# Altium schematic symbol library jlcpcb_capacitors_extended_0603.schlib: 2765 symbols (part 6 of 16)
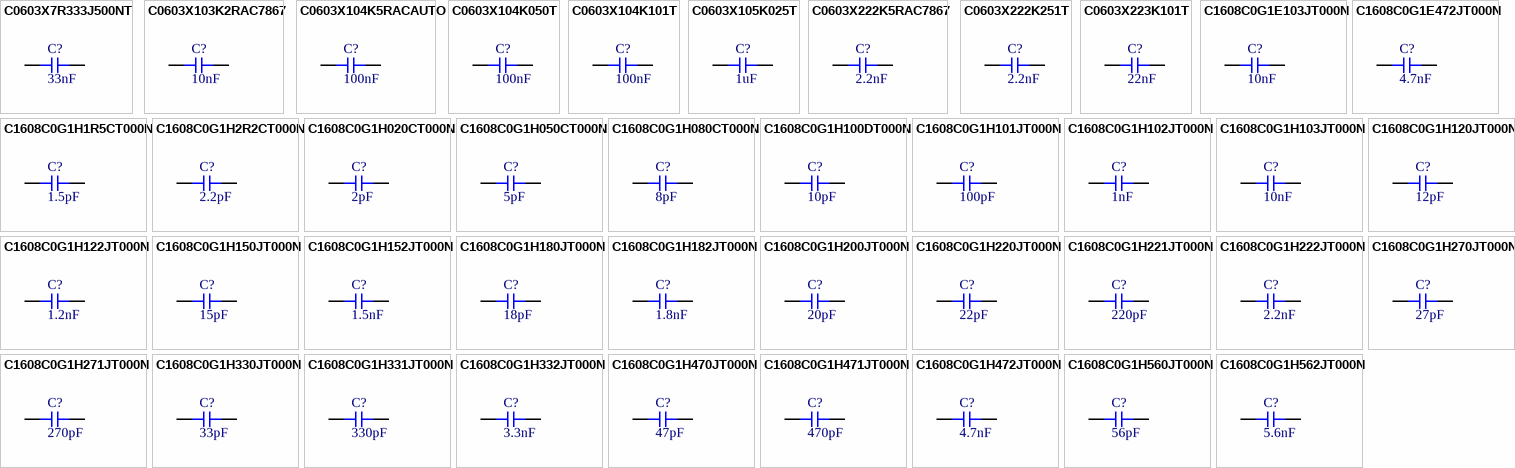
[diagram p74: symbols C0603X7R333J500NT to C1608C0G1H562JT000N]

## C1608C0G1H220JT000N
designator C?  Capacitance: 22pF  (hidden comment: *)
Capacitor, Ceramic (MLCC), 22pF, ±5%, 50V, C0G, ±5%, SMD 0603; Manufacturer: TDK; Manufacturer Part Number: C1608C0G1H220JT000N
footprint CAP-0603 (0603 (1608M) Capacitor)
pins: 1, 2

## C1608C0G1H221JT000N
designator C?  Capacitance: 220pF  (hidden comment: *)
Capacitor, Ceramic (MLCC), 220pF, ±5%, 50V, C0G, ±5%, SMD 0603; Manufacturer: TDK; Manufacturer Part Number: C1608C0G1H221JT000N
footprint CAP-0603 (0603 (1608M) Capacitor)
pins: 1, 2

## C1608C0G1H222JT000N
designator C?  Capacitance: 2.2nF  (hidden comment: *)
Capacitor, Ceramic (MLCC), 2.2nF, ±5%, 50V, C0G, ±5%, SMD 0603; Manufacturer: TDK; Manufacturer Part Number: C1608C0G1H222JT000N
footprint CAP-0603 (0603 (1608M) Capacitor)
pins: 1, 2

## C1608C0G1H270JT000N
designator C?  Capacitance: 27pF  (hidden comment: *)
Capacitor, Ceramic (MLCC), 27pF, ±5%, 50V, C0G, ±5%, SMD 0603; Manufacturer: TDK; Manufacturer Part Number: C1608C0G1H270JT000N
footprint CAP-0603 (0603 (1608M) Capacitor)
pins: 1, 2

## C1608C0G1H271JT000N
designator C?  Capacitance: 270pF  (hidden comment: *)
Capacitor, Ceramic (MLCC), 270pF, ±5%, 50V, C0G, ±5%, SMD 0603; Manufacturer: TDK; Manufacturer Part Number: C1608C0G1H271JT000N
footprint CAP-0603 (0603 (1608M) Capacitor)
pins: 1, 2

## C1608C0G1H330JT000N
designator C?  Capacitance: 33pF  (hidden comment: *)
Capacitor, Ceramic (MLCC), 33pF, ±5%, 50V, C0G, ±5%, SMD 0603; Manufacturer: TDK; Manufacturer Part Number: C1608C0G1H330JT000N
footprint CAP-0603 (0603 (1608M) Capacitor)
pins: 1, 2

## C1608C0G1H331JT000N
designator C?  Capacitance: 330pF  (hidden comment: *)
Capacitor, Ceramic (MLCC), 330pF, ±5%, 50V, C0G, ±5%, SMD 0603; Manufacturer: TDK; Manufacturer Part Number: C1608C0G1H331JT000N
footprint CAP-0603 (0603 (1608M) Capacitor)
pins: 1, 2

## C1608C0G1H332JT000N
designator C?  Capacitance: 3.3nF  (hidden comment: *)
Capacitor, Ceramic (MLCC), 3.3nF, ±5%, 50V, C0G, ±5%, SMD 0603; Manufacturer: TDK; Manufacturer Part Number: C1608C0G1H332JT000N
footprint CAP-0603 (0603 (1608M) Capacitor)
pins: 1, 2

## C1608C0G1H470JT000N
designator C?  Capacitance: 47pF  (hidden comment: *)
Capacitor, Ceramic (MLCC), 47pF, ±5%, 50V, C0G, ±5%, SMD 0603; Manufacturer: TDK; Manufacturer Part Number: C1608C0G1H470JT000N
footprint CAP-0603 (0603 (1608M) Capacitor)
pins: 1, 2

## C1608C0G1H471JT000N
designator C?  Capacitance: 470pF  (hidden comment: *)
Capacitor, Ceramic (MLCC), 470pF, ±5%, 50V, C0G, ±5%, SMD 0603; Manufacturer: TDK; Manufacturer Part Number: C1608C0G1H471JT000N
footprint CAP-0603 (0603 (1608M) Capacitor)
pins: 1, 2

## C1608C0G1H472JT000N
designator C?  Capacitance: 4.7nF  (hidden comment: *)
Capacitor, Ceramic (MLCC), 4.7nF, ±5%, 50V, C0G, ±5%, SMD 0603; Manufacturer: TDK; Manufacturer Part Number: C1608C0G1H472JT000N
footprint CAP-0603 (0603 (1608M) Capacitor)
pins: 1, 2

## C1608C0G1H560JT000N
designator C?  Capacitance: 56pF  (hidden comment: *)
Capacitor, Ceramic (MLCC), 56pF, ±5%, 50V, C0G, ±5%, SMD 0603; Manufacturer: TDK; Manufacturer Part Number: C1608C0G1H560JT000N
footprint CAP-0603 (0603 (1608M) Capacitor)
pins: 1, 2

## C1608C0G1H562JT000N
designator C?  Capacitance: 5.6nF  (hidden comment: *)
Capacitor, Ceramic (MLCC), 5.6nF, ±5%, 50V, C0G, ±5%, SMD 0603; Manufacturer: TDK; Manufacturer Part Number: C1608C0G1H562JT000N
footprint CAP-0603 (0603 (1608M) Capacitor)
pins: 1, 2

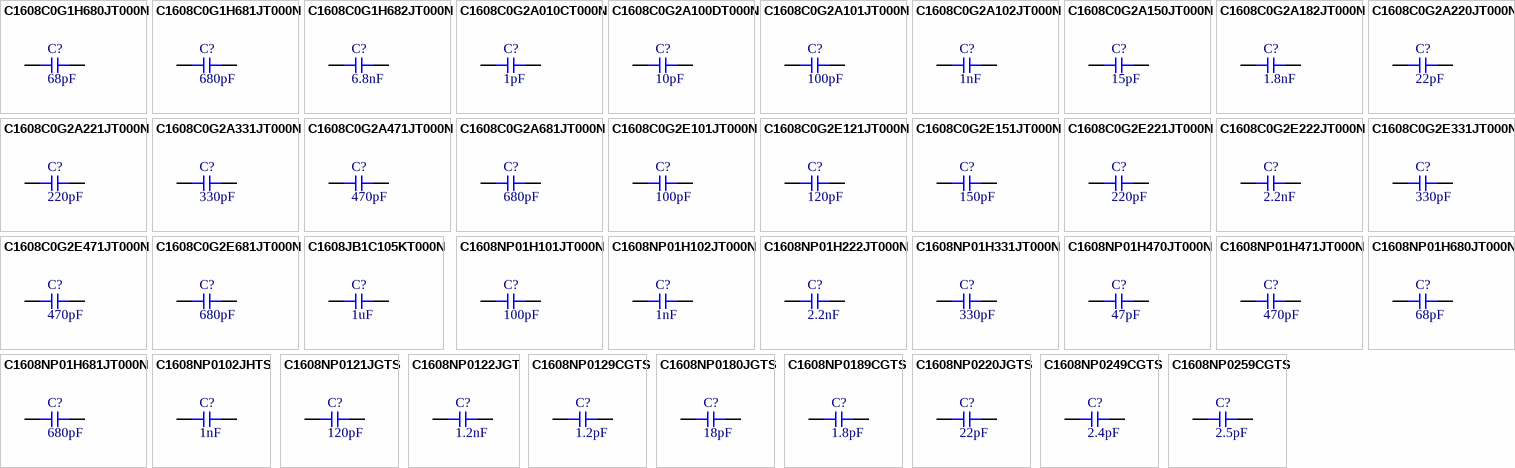
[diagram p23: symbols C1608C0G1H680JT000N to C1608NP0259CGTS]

## C1608C0G1H680JT000N
designator C?  Capacitance: 68pF  (hidden comment: *)
Capacitor, Ceramic (MLCC), 68pF, ±5%, 50V, C0G, ±5%, SMD 0603; Manufacturer: TDK; Manufacturer Part Number: C1608C0G1H680JT000N
footprint CAP-0603 (0603 (1608M) Capacitor)
pins: 1, 2

## C1608C0G1H681JT000N
designator C?  Capacitance: 680pF  (hidden comment: *)
Capacitor, Ceramic (MLCC), 680pF, ±5%, 50V, C0G, ±5%, SMD 0603; Manufacturer: TDK; Manufacturer Part Number: C1608C0G1H681JT000N
footprint CAP-0603 (0603 (1608M) Capacitor)
pins: 1, 2

## C1608C0G1H682JT000N
designator C?  Capacitance: 6.8nF  (hidden comment: *)
Capacitor, Ceramic (MLCC), 6.8nF, ±5%, 50V, C0G, ±5%, SMD 0603; Manufacturer: TDK; Manufacturer Part Number: C1608C0G1H682JT000N
footprint CAP-0603 (0603 (1608M) Capacitor)
pins: 1, 2

## C1608C0G2A010CT000N
designator C?  Capacitance: 1pF  (hidden comment: *)
Capacitor, Ceramic (MLCC), 1pF, ±0.25pF, 100V, C0G, ±0.25pF, SMD 0603; Manufacturer: TDK; Manufacturer Part Number: C1608C0G2A010CT000N
footprint CAP-0603 (0603 (1608M) Capacitor)
pins: 1, 2

## C1608C0G2A100DT000N
designator C?  Capacitance: 10pF  (hidden comment: *)
Capacitor, Ceramic (MLCC), 10pF, ±0.5pF, 100V, C0G, ±0.5pF, SMD 0603; Manufacturer: TDK; Manufacturer Part Number: C1608C0G2A100DT000N
footprint CAP-0603 (0603 (1608M) Capacitor)
pins: 1, 2

## C1608C0G2A101JT000N
designator C?  Capacitance: 100pF  (hidden comment: *)
Capacitor, Ceramic (MLCC), 100pF, ±5%, 100V, C0G, ±5%, SMD 0603; Manufacturer: TDK; Manufacturer Part Number: C1608C0G2A101JT000N
footprint CAP-0603 (0603 (1608M) Capacitor)
pins: 1, 2

## C1608C0G2A102JT000N
designator C?  Capacitance: 1nF  (hidden comment: *)
Capacitor, Ceramic (MLCC), 1nF, ±5%, 100V, C0G, ±5%, SMD 0603; Manufacturer: TDK; Manufacturer Part Number: C1608C0G2A102JT000N
footprint CAP-0603 (0603 (1608M) Capacitor)
pins: 1, 2

## C1608C0G2A150JT000N
designator C?  Capacitance: 15pF  (hidden comment: *)
Capacitor, Ceramic (MLCC), 15pF, ±5%, 100V, C0G, ±5%, SMD 0603; Manufacturer: TDK; Manufacturer Part Number: C1608C0G2A150JT000N
footprint CAP-0603 (0603 (1608M) Capacitor)
pins: 1, 2

## C1608C0G2A182JT000N
designator C?  Capacitance: 1.8nF  (hidden comment: *)
Capacitor, Ceramic (MLCC), 1.8nF, ±5%, 100V, C0G, ±5%, SMD 0603; Manufacturer: TDK; Manufacturer Part Number: C1608C0G2A182JT000N
footprint CAP-0603 (0603 (1608M) Capacitor)
pins: 1, 2

## C1608C0G2A220JT000N
designator C?  Capacitance: 22pF  (hidden comment: *)
Capacitor, Ceramic (MLCC), 22pF, ±5%, 100V, C0G, ±5%, SMD 0603; Manufacturer: TDK; Manufacturer Part Number: C1608C0G2A220JT000N
footprint CAP-0603 (0603 (1608M) Capacitor)
pins: 1, 2

## C1608C0G2A221JT000N
designator C?  Capacitance: 220pF  (hidden comment: *)
Capacitor, Ceramic (MLCC), 220pF, ±5%, 100V, C0G, ±5%, SMD 0603; Manufacturer: TDK; Manufacturer Part Number: C1608C0G2A221JT000N
footprint CAP-0603 (0603 (1608M) Capacitor)
pins: 1, 2

## C1608C0G2A331JT000N
designator C?  Capacitance: 330pF  (hidden comment: *)
Capacitor, Ceramic (MLCC), 330pF, ±5%, 100V, C0G, ±5%, SMD 0603; Manufacturer: TDK; Manufacturer Part Number: C1608C0G2A331JT000N
footprint CAP-0603 (0603 (1608M) Capacitor)
pins: 1, 2

## C1608C0G2A471JT000N
designator C?  Capacitance: 470pF  (hidden comment: *)
Capacitor, Ceramic (MLCC), 470pF, ±5%, 100V, C0G, ±5%, SMD 0603; Manufacturer: TDK; Manufacturer Part Number: C1608C0G2A471JT000N
footprint CAP-0603 (0603 (1608M) Capacitor)
pins: 1, 2

## C1608C0G2A681JT000N
designator C?  Capacitance: 680pF  (hidden comment: *)
Capacitor, Ceramic (MLCC), 680pF, ±5%, 100V, C0G, ±5%, SMD 0603; Manufacturer: TDK; Manufacturer Part Number: C1608C0G2A681JT000N
footprint CAP-0603 (0603 (1608M) Capacitor)
pins: 1, 2

## C1608C0G2E101JT000N
designator C?  Capacitance: 100pF  (hidden comment: *)
Capacitor, Ceramic (MLCC), 100pF, ±5%, 250V, C0G, ±5%, SMD 0603; Manufacturer: TDK; Manufacturer Part Number: C1608C0G2E101JT000N
footprint CAP-0603 (0603 (1608M) Capacitor)
pins: 1, 2

## C1608C0G2E121JT000N
designator C?  Capacitance: 120pF  (hidden comment: *)
Capacitor, Ceramic (MLCC), 120pF, ±5%, 250V, C0G, ±5%, SMD 0603; Manufacturer: TDK; Manufacturer Part Number: C1608C0G2E121JT000N
footprint CAP-0603 (0603 (1608M) Capacitor)
pins: 1, 2

## C1608C0G2E151JT000N
designator C?  Capacitance: 150pF  (hidden comment: *)
Capacitor, Ceramic (MLCC), 150pF, ±5%, 250V, C0G, ±5%, SMD 0603; Manufacturer: TDK; Manufacturer Part Number: C1608C0G2E151JT000N
footprint CAP-0603 (0603 (1608M) Capacitor)
pins: 1, 2

## C1608C0G2E221JT000N
designator C?  Capacitance: 220pF  (hidden comment: *)
Capacitor, Ceramic (MLCC), 220pF, ±5%, 250V, C0G, ±5%, SMD 0603; Manufacturer: TDK; Manufacturer Part Number: C1608C0G2E221JT000N
footprint CAP-0603 (0603 (1608M) Capacitor)
pins: 1, 2

## C1608C0G2E222JT000N
designator C?  Capacitance: 2.2nF  (hidden comment: *)
Capacitor, Ceramic (MLCC), 2.2nF, ±5%, 250V, C0G, ±5%, SMD 0603; Manufacturer: TDK; Manufacturer Part Number: C1608C0G2E222JT000N
footprint CAP-0603 (0603 (1608M) Capacitor)
pins: 1, 2

## C1608C0G2E331JT000N
designator C?  Capacitance: 330pF  (hidden comment: *)
Capacitor, Ceramic (MLCC), 330pF, ±5%, 250V, C0G, ±5%, SMD 0603; Manufacturer: TDK; Manufacturer Part Number: C1608C0G2E331JT000N
footprint CAP-0603 (0603 (1608M) Capacitor)
pins: 1, 2

## C1608C0G2E471JT000N
designator C?  Capacitance: 470pF  (hidden comment: *)
Capacitor, Ceramic (MLCC), 470pF, ±5%, 250V, C0G, ±5%, SMD 0603; Manufacturer: TDK; Manufacturer Part Number: C1608C0G2E471JT000N
footprint CAP-0603 (0603 (1608M) Capacitor)
pins: 1, 2

## C1608C0G2E681JT000N
designator C?  Capacitance: 680pF  (hidden comment: *)
Capacitor, Ceramic (MLCC), 680pF, ±5%, 250V, C0G, ±5%, SMD 0603; Manufacturer: TDK; Manufacturer Part Number: C1608C0G2E681JT000N
footprint CAP-0603 (0603 (1608M) Capacitor)
pins: 1, 2

## C1608JB1C105KT000N
designator C?  Capacitance: 1uF  (hidden comment: *)
Capacitor, Ceramic (MLCC), 1uF, ±10%, 16V, ±10%, SMD 0603; Manufacturer: TDK; Manufacturer Part Number: C1608JB1C105KT000N
footprint CAP-0603 (0603 (1608M) Capacitor)
pins: 1, 2

## C1608NP01H101JT000N
designator C?  Capacitance: 100pF  (hidden comment: *)
Capacitor, Ceramic (MLCC), 100pF, ±5%, 50V, NP0, ±5%, SMD 0603; Manufacturer: TDK; Manufacturer Part Number: C1608NP01H101JT000N
footprint CAP-0603 (0603 (1608M) Capacitor)
pins: 1, 2

## C1608NP01H102JT000N
designator C?  Capacitance: 1nF  (hidden comment: *)
Capacitor, Ceramic (MLCC), 1nF, ±5%, 50V, NP0, ±5%, SMD 0603; Manufacturer: TDK; Manufacturer Part Number: C1608NP01H102JT000N
footprint CAP-0603 (0603 (1608M) Capacitor)
pins: 1, 2

## C1608NP01H222JT000N
designator C?  Capacitance: 2.2nF  (hidden comment: *)
Capacitor, Ceramic (MLCC), 2.2nF, ±5%, 50V, NP0, ±5%, SMD 0603; Manufacturer: TDK; Manufacturer Part Number: C1608NP01H222JT000N
footprint CAP-0603 (0603 (1608M) Capacitor)
pins: 1, 2

## C1608NP01H331JT000N
designator C?  Capacitance: 330pF  (hidden comment: *)
Capacitor, Ceramic (MLCC), 330pF, ±5%, 50V, NP0, ±5%, SMD 0603; Manufacturer: TDK; Manufacturer Part Number: C1608NP01H331JT000N
footprint CAP-0603 (0603 (1608M) Capacitor)
pins: 1, 2

## C1608NP01H470JT000N
designator C?  Capacitance: 47pF  (hidden comment: *)
Capacitor, Ceramic (MLCC), 47pF, ±5%, 50V, NP0, ±5%, SMD 0603; Manufacturer: TDK; Manufacturer Part Number: C1608NP01H470JT000N
footprint CAP-0603 (0603 (1608M) Capacitor)
pins: 1, 2

## C1608NP01H471JT000N
designator C?  Capacitance: 470pF  (hidden comment: *)
Capacitor, Ceramic (MLCC), 470pF, ±5%, 50V, NP0, ±5%, SMD 0603; Manufacturer: TDK; Manufacturer Part Number: C1608NP01H471JT000N
footprint CAP-0603 (0603 (1608M) Capacitor)
pins: 1, 2

## C1608NP01H680JT000N
designator C?  Capacitance: 68pF  (hidden comment: *)
Capacitor, Ceramic (MLCC), 68pF, ±5%, 50V, NP0, ±5%, SMD 0603; Manufacturer: TDK; Manufacturer Part Number: C1608NP01H680JT000N
footprint CAP-0603 (0603 (1608M) Capacitor)
pins: 1, 2

## C1608NP01H681JT000N
designator C?  Capacitance: 680pF  (hidden comment: *)
Capacitor, Ceramic (MLCC), 680pF, ±5%, 50V, NP0, ±5%, SMD 0603; Manufacturer: TDK; Manufacturer Part Number: C1608NP01H681JT000N
footprint CAP-0603 (0603 (1608M) Capacitor)
pins: 1, 2

## C1608NP0102JHTS
designator C?  Capacitance: 1nF  (hidden comment: *)
Capacitor, Ceramic (MLCC), 1nF, ±5%, 100V, NP0, ±5%, SMD 0603; Manufacturer: Darfon Elec; Manufacturer Part Number: C1608NP0102JHTS
footprint CAP-0603 (0603 (1608M) Capacitor)
pins: 1, 2

## C1608NP0121JGTS
designator C?  Capacitance: 120pF  (hidden comment: *)
Capacitor, Ceramic (MLCC), 120pF, ±5%, 50V, NP0, ±5%, SMD 0603; Manufacturer: Darfon Elec; Manufacturer Part Number: C1608NP0121JGTS
footprint CAP-0603 (0603 (1608M) Capacitor)
pins: 1, 2

## C1608NP0122JGT
designator C?  Capacitance: 1.2nF  (hidden comment: *)
Capacitor, Ceramic (MLCC), 1.2nF, ±5%, 50V, NP0, ±5%, SMD 0603; Manufacturer: Darfon Elec; Manufacturer Part Number: C1608NP0122JGT
footprint CAP-0603 (0603 (1608M) Capacitor)
pins: 1, 2

## C1608NP0129CGTS
designator C?  Capacitance: 1.2pF  (hidden comment: *)
Capacitor, Ceramic (MLCC), 1.2pF, ±0.25pF, 50V, NP0, ±0.25pF, SMD 0603; Manufacturer: Darfon Elec; Manufacturer Part Number: C1608NP0129CGTS
footprint CAP-0603 (0603 (1608M) Capacitor)
pins: 1, 2

## C1608NP0180JGTS
designator C?  Capacitance: 18pF  (hidden comment: *)
Capacitor, Ceramic (MLCC), 18pF, ±5%, 50V, NP0, ±5%, SMD 0603; Manufacturer: Darfon Elec; Manufacturer Part Number: C1608NP0180JGTS
footprint CAP-0603 (0603 (1608M) Capacitor)
pins: 1, 2

## C1608NP0189CGTS
designator C?  Capacitance: 1.8pF  (hidden comment: *)
Capacitor, Ceramic (MLCC), 1.8pF, ±0.25pF, 50V, NP0, ±0.25pF, SMD 0603; Manufacturer: Darfon Elec; Manufacturer Part Number: C1608NP0189CGTS
footprint CAP-0603 (0603 (1608M) Capacitor)
pins: 1, 2

## C1608NP0220JGTS
designator C?  Capacitance: 22pF  (hidden comment: *)
Capacitor, Ceramic (MLCC), 22pF, ±5%, 50V, NP0, ±5%, SMD 0603; Manufacturer: Darfon Elec; Manufacturer Part Number: C1608NP0220JGTS
footprint CAP-0603 (0603 (1608M) Capacitor)
pins: 1, 2

## C1608NP0249CGTS
designator C?  Capacitance: 2.4pF  (hidden comment: *)
Capacitor, Ceramic (MLCC), 2.4pF, ±0.25pF, 50V, NP0, ±0.25pF, SMD 0603; Manufacturer: Darfon Elec; Manufacturer Part Number: C1608NP0249CGTS
footprint CAP-0603 (0603 (1608M) Capacitor)
pins: 1, 2

## C1608NP0259CGTS
designator C?  Capacitance: 2.5pF  (hidden comment: *)
Capacitor, Ceramic (MLCC), 2.5pF, ±0.25pF, 50V, NP0, ±0.25pF, SMD 0603; Manufacturer: Darfon Elec; Manufacturer Part Number: C1608NP0259CGTS
footprint CAP-0603 (0603 (1608M) Capacitor)
pins: 1, 2

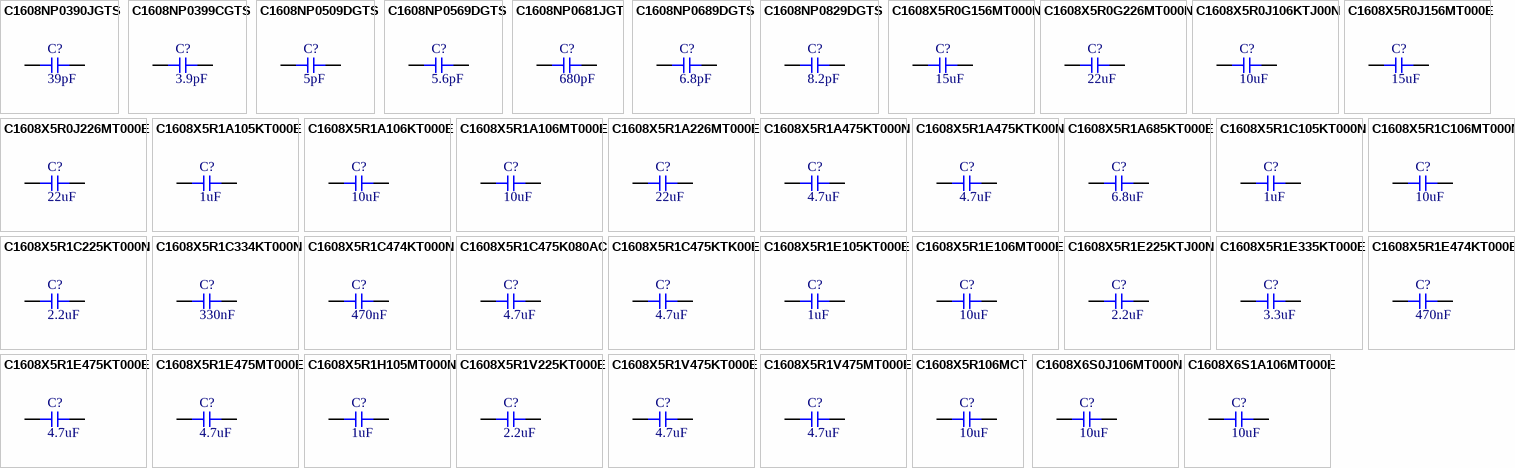
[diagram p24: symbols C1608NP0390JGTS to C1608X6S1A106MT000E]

## C1608NP0390JGTS
designator C?  Capacitance: 39pF  (hidden comment: *)
Capacitor, Ceramic (MLCC), 39pF, ±5%, 50V, NP0, ±5%, SMD 0603; Manufacturer: Darfon Elec; Manufacturer Part Number: C1608NP0390JGTS
footprint CAP-0603 (0603 (1608M) Capacitor)
pins: 1, 2

## C1608NP0399CGTS
designator C?  Capacitance: 3.9pF  (hidden comment: *)
Capacitor, Ceramic (MLCC), 3.9pF, ±0.25pF, 50V, NP0, ±0.25pF, SMD 0603; Manufacturer: Darfon Elec; Manufacturer Part Number: C1608NP0399CGTS
footprint CAP-0603 (0603 (1608M) Capacitor)
pins: 1, 2

## C1608NP0509DGTS
designator C?  Capacitance: 5pF  (hidden comment: *)
Capacitor, Ceramic (MLCC), 5pF, ±0.5pF, 50V, NP0, ±0.5pF, SMD 0603; Manufacturer: Darfon Elec; Manufacturer Part Number: C1608NP0509DGTS
footprint CAP-0603 (0603 (1608M) Capacitor)
pins: 1, 2

## C1608NP0569DGTS
designator C?  Capacitance: 5.6pF  (hidden comment: *)
Capacitor, Ceramic (MLCC), 5.6pF, ±0.5pF, 50V, NP0, ±0.5pF, SMD 0603; Manufacturer: Darfon Elec; Manufacturer Part Number: C1608NP0569DGTS
footprint CAP-0603 (0603 (1608M) Capacitor)
pins: 1, 2

## C1608NP0681JGT
designator C?  Capacitance: 680pF  (hidden comment: *)
Capacitor, Ceramic (MLCC), 680pF, ±5%, 50V, NP0, ±5%, SMD 0603; Manufacturer: Darfon Elec; Manufacturer Part Number: C1608NP0681JGT
footprint CAP-0603 (0603 (1608M) Capacitor)
pins: 1, 2

## C1608NP0689DGTS
designator C?  Capacitance: 6.8pF  (hidden comment: *)
Capacitor, Ceramic (MLCC), 6.8pF, ±0.5pF, 50V, NP0, ±0.5pF, SMD 0603; Manufacturer: Darfon Elec; Manufacturer Part Number: C1608NP0689DGTS
footprint CAP-0603 (0603 (1608M) Capacitor)
pins: 1, 2

## C1608NP0829DGTS
designator C?  Capacitance: 8.2pF  (hidden comment: *)
Capacitor, Ceramic (MLCC), 8.2pF, ±0.5pF, 50V, NP0, ±0.5pF, SMD 0603; Manufacturer: Darfon Elec; Manufacturer Part Number: C1608NP0829DGTS
footprint CAP-0603 (0603 (1608M) Capacitor)
pins: 1, 2

## C1608X5R0G156MT000N
designator C?  Capacitance: 15uF  (hidden comment: *)
Capacitor, Ceramic (MLCC), 15uF, ±20%, 4V, X5R, ±20%, SMD 0603; Manufacturer: TDK; Manufacturer Part Number: C1608X5R0G156MT000N
footprint CAP-0603 (0603 (1608M) Capacitor)
pins: 1, 2

## C1608X5R0G226MT000N
designator C?  Capacitance: 22uF  (hidden comment: *)
Capacitor, Ceramic (MLCC), 22uF, ±20%, 4V, X5R, ±20%, SMD 0603; Manufacturer: TDK; Manufacturer Part Number: C1608X5R0G226MT000N
footprint CAP-0603 (0603 (1608M) Capacitor)
pins: 1, 2

## C1608X5R0J106KTJ00N
designator C?  Capacitance: 10uF  (hidden comment: *)
Capacitor, Ceramic (MLCC), 10uF, ±10%, 6.3V, X5R, ±10%, SMD 0603; Manufacturer: TDK; Manufacturer Part Number: C1608X5R0J106KTJ00N
footprint CAP-0603 (0603 (1608M) Capacitor)
pins: 1, 2

## C1608X5R0J156MT000E
designator C?  Capacitance: 15uF  (hidden comment: *)
Capacitor, Ceramic (MLCC), 15uF, ±20%, 6.3V, X5R, ±20%, SMD 0603; Manufacturer: TDK; Manufacturer Part Number: C1608X5R0J156MT000E
footprint CAP-0603 (0603 (1608M) Capacitor)
pins: 1, 2

## C1608X5R0J226MT000E
designator C?  Capacitance: 22uF  (hidden comment: *)
Capacitor, Ceramic (MLCC), 22uF, ±20%, 6.3V, X5R, ±20%, SMD 0603; Manufacturer: TDK; Manufacturer Part Number: C1608X5R0J226MT000E
footprint CAP-0603 (0603 (1608M) Capacitor)
pins: 1, 2

## C1608X5R1A105KT000E
designator C?  Capacitance: 1uF  (hidden comment: *)
Capacitor, Ceramic (MLCC), 1uF, ±10%, 10V, X5R, ±10%, SMD 0603; Manufacturer: TDK; Manufacturer Part Number: C1608X5R1A105KT000E
footprint CAP-0603 (0603 (1608M) Capacitor)
pins: 1, 2

## C1608X5R1A106KT000E
designator C?  Capacitance: 10uF  (hidden comment: *)
Capacitor, Ceramic (MLCC), 10uF, ±10%, 10V, X5R, ±10%, SMD 0603; Manufacturer: TDK; Manufacturer Part Number: C1608X5R1A106KT000E
footprint CAP-0603 (0603 (1608M) Capacitor)
pins: 1, 2

## C1608X5R1A106MT000E
designator C?  Capacitance: 10uF  (hidden comment: *)
Capacitor, Ceramic (MLCC), 10uF, ±20%, 10V, X5R, ±20%, SMD 0603; Manufacturer: TDK; Manufacturer Part Number: C1608X5R1A106MT000E
footprint CAP-0603 (0603 (1608M) Capacitor)
pins: 1, 2

## C1608X5R1A226MT000E
designator C?  Capacitance: 22uF  (hidden comment: *)
Capacitor, Ceramic (MLCC), 22uF, ±20%, 10V, X5R, ±20%, SMD 0603; Manufacturer: TDK; Manufacturer Part Number: C1608X5R1A226MT000E
footprint CAP-0603 (0603 (1608M) Capacitor)
pins: 1, 2

## C1608X5R1A475KT000N
designator C?  Capacitance: 4.7uF  (hidden comment: *)
Capacitor, Ceramic (MLCC), 4.7uF, ±10%, 10V, X5R, ±10%, SMD 0603; Manufacturer: TDK; Manufacturer Part Number: C1608X5R1A475KT000N
footprint CAP-0603 (0603 (1608M) Capacitor)
pins: 1, 2

## C1608X5R1A475KTK00N
designator C?  Capacitance: 4.7uF  (hidden comment: *)
Capacitor, Ceramic (MLCC), 4.7uF, ±10%, 10V, X5R, ±10%, SMD 0603; Manufacturer: TDK; Manufacturer Part Number: C1608X5R1A475KTK00N
footprint CAP-0603 (0603 (1608M) Capacitor)
pins: 1, 2

## C1608X5R1A685KT000E
designator C?  Capacitance: 6.8uF  (hidden comment: *)
Capacitor, Ceramic (MLCC), 6.8uF, ±10%, 10V, X5R, ±10%, SMD 0603; Manufacturer: TDK; Manufacturer Part Number: C1608X5R1A685KT000E
footprint CAP-0603 (0603 (1608M) Capacitor)
pins: 1, 2

## C1608X5R1C105KT000N
designator C?  Capacitance: 1uF  (hidden comment: *)
Capacitor, Ceramic (MLCC), 1uF, ±10%, 16V, X5R, ±10%, SMD 0603; Manufacturer: TDK; Manufacturer Part Number: C1608X5R1C105KT000N
footprint CAP-0603 (0603 (1608M) Capacitor)
pins: 1, 2

## C1608X5R1C106MT000N
designator C?  Capacitance: 10uF  (hidden comment: *)
Capacitor, Ceramic (MLCC), 10uF, ±20%, 16V, X5R, ±20%, SMD 0603; Manufacturer: TDK; Manufacturer Part Number: C1608X5R1C106MT000N
footprint CAP-0603 (0603 (1608M) Capacitor)
pins: 1, 2

## C1608X5R1C225KT000N
designator C?  Capacitance: 2.2uF  (hidden comment: *)
Capacitor, Ceramic (MLCC), 2.2uF, ±10%, 16V, X5R, ±10%, SMD 0603; Manufacturer: TDK; Manufacturer Part Number: C1608X5R1C225KT000N
footprint CAP-0603 (0603 (1608M) Capacitor)
pins: 1, 2

## C1608X5R1C334KT000N
designator C?  Capacitance: 330nF  (hidden comment: *)
Capacitor, Ceramic (MLCC), 330nF, ±10%, 16V, X5R, ±10%, SMD 0603; Manufacturer: TDK; Manufacturer Part Number: C1608X5R1C334KT000N
footprint CAP-0603 (0603 (1608M) Capacitor)
pins: 1, 2

## C1608X5R1C474KT000N
designator C?  Capacitance: 470nF  (hidden comment: *)
Capacitor, Ceramic (MLCC), 470nF, ±10%, 16V, X5R, ±10%, SMD 0603; Manufacturer: TDK; Manufacturer Part Number: C1608X5R1C474KT000N
footprint CAP-0603 (0603 (1608M) Capacitor)
pins: 1, 2

## C1608X5R1C475K080AC
designator C?  Capacitance: 4.7uF  (hidden comment: *)
Capacitor, Ceramic (MLCC), 4.7uF, ±10%, 16V, X5R, ±10%, SMD 0603; Manufacturer: TDK; Manufacturer Part Number: C1608X5R1C475K080AC
footprint CAP-0603 (0603 (1608M) Capacitor)
pins: 1, 2

## C1608X5R1C475KTK00E
designator C?  Capacitance: 4.7uF  (hidden comment: *)
Capacitor, Ceramic (MLCC), 4.7uF, ±10%, 16V, X5R, ±10%, SMD 0603; Manufacturer: TDK; Manufacturer Part Number: C1608X5R1C475KTK00E
footprint CAP-0603 (0603 (1608M) Capacitor)
pins: 1, 2

## C1608X5R1E105KT000E
designator C?  Capacitance: 1uF  (hidden comment: *)
Capacitor, Ceramic (MLCC), 1uF, ±10%, 25V, X5R, ±10%, SMD 0603; Manufacturer: TDK; Manufacturer Part Number: C1608X5R1E105KT000E
footprint CAP-0603 (0603 (1608M) Capacitor)
pins: 1, 2

## C1608X5R1E106MT000E
designator C?  Capacitance: 10uF  (hidden comment: *)
Capacitor, Ceramic (MLCC), 10uF, ±20%, 25V, X5R, ±20%, SMD 0603; Manufacturer: TDK; Manufacturer Part Number: C1608X5R1E106MT000E
footprint CAP-0603 (0603 (1608M) Capacitor)
pins: 1, 2

## C1608X5R1E225KTJ00N
designator C?  Capacitance: 2.2uF  (hidden comment: *)
Capacitor, Ceramic (MLCC), 2.2uF, ±10%, 25V, X5R, ±10%, SMD 0603; Manufacturer: TDK; Manufacturer Part Number: C1608X5R1E225KTJ00N
footprint CAP-0603 (0603 (1608M) Capacitor)
pins: 1, 2

## C1608X5R1E335KT000E
designator C?  Capacitance: 3.3uF  (hidden comment: *)
Capacitor, Ceramic (MLCC), 3.3uF, ±10%, 25V, X5R, ±10%, SMD 0603; Manufacturer: TDK; Manufacturer Part Number: C1608X5R1E335KT000E
footprint CAP-0603 (0603 (1608M) Capacitor)
pins: 1, 2

## C1608X5R1E474KT000E
designator C?  Capacitance: 470nF  (hidden comment: *)
Capacitor, Ceramic (MLCC), 470nF, ±10%, 25V, X5R, ±10%, SMD 0603; Manufacturer: TDK; Manufacturer Part Number: C1608X5R1E474KT000E
footprint CAP-0603 (0603 (1608M) Capacitor)
pins: 1, 2

## C1608X5R1E475KT000E
designator C?  Capacitance: 4.7uF  (hidden comment: *)
Capacitor, Ceramic (MLCC), 4.7uF, ±10%, 25V, X5R, ±10%, SMD 0603; Manufacturer: TDK; Manufacturer Part Number: C1608X5R1E475KT000E
footprint CAP-0603 (0603 (1608M) Capacitor)
pins: 1, 2

## C1608X5R1E475MT000E
designator C?  Capacitance: 4.7uF  (hidden comment: *)
Capacitor, Ceramic (MLCC), 4.7uF, ±20%, 25V, X5R, ±20%, SMD 0603; Manufacturer: TDK; Manufacturer Part Number: C1608X5R1E475MT000E
footprint CAP-0603 (0603 (1608M) Capacitor)
pins: 1, 2

## C1608X5R1H105MT000N
designator C?  Capacitance: 1uF  (hidden comment: *)
Capacitor, Ceramic (MLCC), 1uF, ±20%, 50V, X5R, ±20%, SMD 0603; Manufacturer: TDK; Manufacturer Part Number: C1608X5R1H105MT000N
footprint CAP-0603 (0603 (1608M) Capacitor)
pins: 1, 2

## C1608X5R1V225KT000E
designator C?  Capacitance: 2.2uF  (hidden comment: *)
Capacitor, Ceramic (MLCC), 2.2uF, ±10%, 35V, X5R, ±10%, SMD 0603; Manufacturer: TDK; Manufacturer Part Number: C1608X5R1V225KT000E
footprint CAP-0603 (0603 (1608M) Capacitor)
pins: 1, 2

## C1608X5R1V475KT000E
designator C?  Capacitance: 4.7uF  (hidden comment: *)
Capacitor, Ceramic (MLCC), 4.7uF, ±10%, 35V, X5R, ±10%, SMD 0603; Manufacturer: TDK; Manufacturer Part Number: C1608X5R1V475KT000E
footprint CAP-0603 (0603 (1608M) Capacitor)
pins: 1, 2

## C1608X5R1V475MT000E
designator C?  Capacitance: 4.7uF  (hidden comment: *)
Capacitor, Ceramic (MLCC), 4.7uF, ±20%, 35V, X5R, ±20%, SMD 0603; Manufacturer: TDK; Manufacturer Part Number: C1608X5R1V475MT000E
footprint CAP-0603 (0603 (1608M) Capacitor)
pins: 1, 2

## C1608X5R106MCT
designator C?  Capacitance: 10uF  (hidden comment: *)
Capacitor, Ceramic (MLCC), 10uF, ±20%, 6.3V, X5R, ±20%, SMD 0603; Manufacturer: Darfon Elec; Manufacturer Part Number: C1608X5R106MCT
footprint CAP-0603 (0603 (1608M) Capacitor)
pins: 1, 2

## C1608X6S0J106MT000N
designator C?  Capacitance: 10uF  (hidden comment: *)
Capacitor, Ceramic (MLCC), 10uF, ±20%, 6.3V, X6S, ±20%, SMD 0603; Manufacturer: TDK; Manufacturer Part Number: C1608X6S0J106MT000N
footprint CAP-0603 (0603 (1608M) Capacitor)
pins: 1, 2

## C1608X6S1A106MT000E
designator C?  Capacitance: 10uF  (hidden comment: *)
Capacitor, Ceramic (MLCC), 10uF, ±20%, 10V, X6S, ±20%, SMD 0603; Manufacturer: TDK; Manufacturer Part Number: C1608X6S1A106MT000E
footprint CAP-0603 (0603 (1608M) Capacitor)
pins: 1, 2

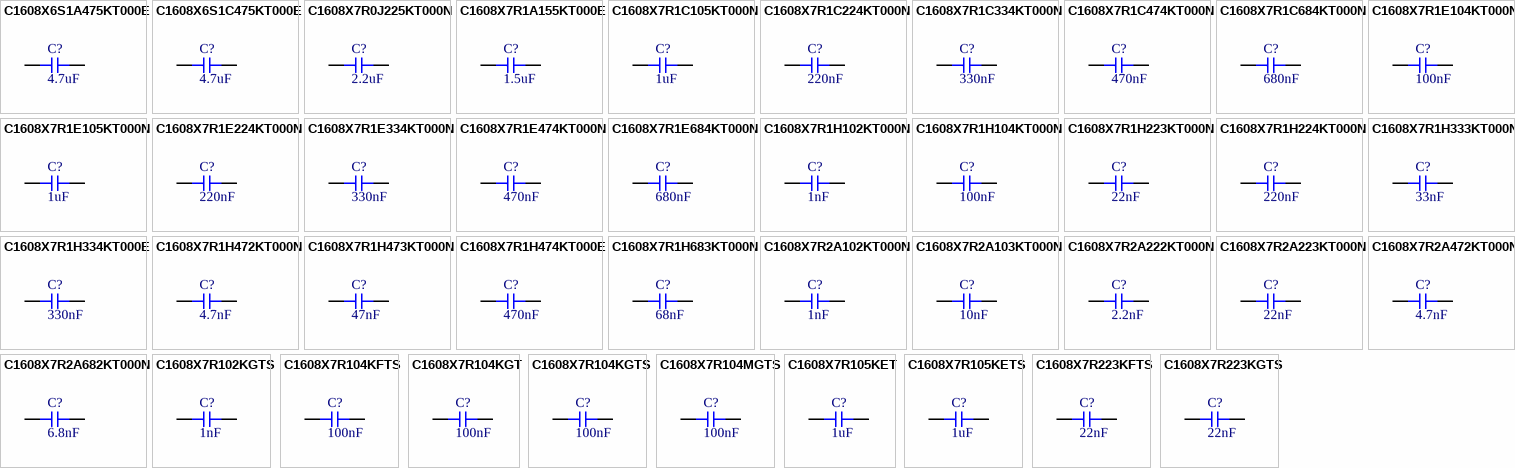
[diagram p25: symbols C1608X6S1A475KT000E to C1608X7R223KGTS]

## C1608X6S1A475KT000E
designator C?  Capacitance: 4.7uF  (hidden comment: *)
Capacitor, Ceramic (MLCC), 4.7uF, ±10%, 10V, X6S, ±10%, SMD 0603; Manufacturer: TDK; Manufacturer Part Number: C1608X6S1A475KT000E
footprint CAP-0603 (0603 (1608M) Capacitor)
pins: 1, 2

## C1608X6S1C475KT000E
designator C?  Capacitance: 4.7uF  (hidden comment: *)
Capacitor, Ceramic (MLCC), 4.7uF, ±10%, 16V, X6S, ±10%, SMD 0603; Manufacturer: TDK; Manufacturer Part Number: C1608X6S1C475KT000E
footprint CAP-0603 (0603 (1608M) Capacitor)
pins: 1, 2

## C1608X7R0J225KT000N
designator C?  Capacitance: 2.2uF  (hidden comment: *)
Capacitor, Ceramic (MLCC), 2.2uF, ±10%, 6.3V, X7R, ±10%, SMD 0603; Manufacturer: TDK; Manufacturer Part Number: C1608X7R0J225KT000N
footprint CAP-0603 (0603 (1608M) Capacitor)
pins: 1, 2

## C1608X7R1A155KT000E
designator C?  Capacitance: 1.5uF  (hidden comment: *)
Capacitor, Ceramic (MLCC), 1.5uF, ±10%, 10V, X7R, ±10%, SMD 0603; Manufacturer: TDK; Manufacturer Part Number: C1608X7R1A155KT000E
footprint CAP-0603 (0603 (1608M) Capacitor)
pins: 1, 2

## C1608X7R1C105KT000N
designator C?  Capacitance: 1uF  (hidden comment: *)
Capacitor, Ceramic (MLCC), 1uF, ±10%, 16V, X7R, ±10%, SMD 0603; Manufacturer: TDK; Manufacturer Part Number: C1608X7R1C105KT000N
footprint CAP-0603 (0603 (1608M) Capacitor)
pins: 1, 2

## C1608X7R1C224KT000N
designator C?  Capacitance: 220nF  (hidden comment: *)
Capacitor, Ceramic (MLCC), 220nF, ±10%, 16V, X7R, ±10%, SMD 0603; Manufacturer: TDK; Manufacturer Part Number: C1608X7R1C224KT000N
footprint CAP-0603 (0603 (1608M) Capacitor)
pins: 1, 2

## C1608X7R1C334KT000N
designator C?  Capacitance: 330nF  (hidden comment: *)
Capacitor, Ceramic (MLCC), 330nF, ±10%, 16V, X7R, ±10%, SMD 0603; Manufacturer: TDK; Manufacturer Part Number: C1608X7R1C334KT000N
footprint CAP-0603 (0603 (1608M) Capacitor)
pins: 1, 2

## C1608X7R1C474KT000N
designator C?  Capacitance: 470nF  (hidden comment: *)
Capacitor, Ceramic (MLCC), 470nF, ±10%, 16V, X7R, ±10%, SMD 0603; Manufacturer: TDK; Manufacturer Part Number: C1608X7R1C474KT000N
footprint CAP-0603 (0603 (1608M) Capacitor)
pins: 1, 2

## C1608X7R1C684KT000N
designator C?  Capacitance: 680nF  (hidden comment: *)
Capacitor, Ceramic (MLCC), 680nF, ±10%, 16V, X7R, ±10%, SMD 0603; Manufacturer: TDK; Manufacturer Part Number: C1608X7R1C684KT000N
footprint CAP-0603 (0603 (1608M) Capacitor)
pins: 1, 2

## C1608X7R1E104KT000N
designator C?  Capacitance: 100nF  (hidden comment: *)
Capacitor, Ceramic (MLCC), 100nF, ±10%, 25V, X7R, ±10%, SMD 0603; Manufacturer: TDK; Manufacturer Part Number: C1608X7R1E104KT000N
footprint CAP-0603 (0603 (1608M) Capacitor)
pins: 1, 2

## C1608X7R1E105KT000N
designator C?  Capacitance: 1uF  (hidden comment: *)
Capacitor, Ceramic (MLCC), 1uF, ±10%, 25V, X7R, ±10%, SMD 0603; Manufacturer: TDK; Manufacturer Part Number: C1608X7R1E105KT000N
footprint CAP-0603 (0603 (1608M) Capacitor)
pins: 1, 2

## C1608X7R1E224KT000N
designator C?  Capacitance: 220nF  (hidden comment: *)
Capacitor, Ceramic (MLCC), 220nF, ±10%, 25V, X7R, ±10%, SMD 0603; Manufacturer: TDK; Manufacturer Part Number: C1608X7R1E224KT000N
footprint CAP-0603 (0603 (1608M) Capacitor)
pins: 1, 2

## C1608X7R1E334KT000N
designator C?  Capacitance: 330nF  (hidden comment: *)
Capacitor, Ceramic (MLCC), 330nF, ±10%, 25V, X7R, ±10%, SMD 0603; Manufacturer: TDK; Manufacturer Part Number: C1608X7R1E334KT000N
footprint CAP-0603 (0603 (1608M) Capacitor)
pins: 1, 2

## C1608X7R1E474KT000N
designator C?  Capacitance: 470nF  (hidden comment: *)
Capacitor, Ceramic (MLCC), 470nF, ±10%, 25V, X7R, ±10%, SMD 0603; Manufacturer: TDK; Manufacturer Part Number: C1608X7R1E474KT000N
footprint CAP-0603 (0603 (1608M) Capacitor)
pins: 1, 2

## C1608X7R1E684KT000N
designator C?  Capacitance: 680nF  (hidden comment: *)
Capacitor, Ceramic (MLCC), 680nF, ±10%, 25V, X7R, ±10%, SMD 0603; Manufacturer: TDK; Manufacturer Part Number: C1608X7R1E684KT000N
footprint CAP-0603 (0603 (1608M) Capacitor)
pins: 1, 2

## C1608X7R1H102KT000N
designator C?  Capacitance: 1nF  (hidden comment: *)
Capacitor, Ceramic (MLCC), 1nF, ±10%, 50V, X7R, ±10%, SMD 0603; Manufacturer: TDK; Manufacturer Part Number: C1608X7R1H102KT000N
footprint CAP-0603 (0603 (1608M) Capacitor)
pins: 1, 2

## C1608X7R1H104KT000N
designator C?  Capacitance: 100nF  (hidden comment: *)
Capacitor, Ceramic (MLCC), 100nF, ±10%, 50V, X7R, ±10%, SMD 0603; Manufacturer: TDK; Manufacturer Part Number: C1608X7R1H104KT000N
footprint CAP-0603 (0603 (1608M) Capacitor)
pins: 1, 2

## C1608X7R1H223KT000N
designator C?  Capacitance: 22nF  (hidden comment: *)
Capacitor, Ceramic (MLCC), 22nF, ±10%, 50V, X7R, ±10%, SMD 0603; Manufacturer: TDK; Manufacturer Part Number: C1608X7R1H223KT000N
footprint CAP-0603 (0603 (1608M) Capacitor)
pins: 1, 2

## C1608X7R1H224KT000N
designator C?  Capacitance: 220nF  (hidden comment: *)
Capacitor, Ceramic (MLCC), 220nF, ±10%, 50V, X7R, ±10%, SMD 0603; Manufacturer: TDK; Manufacturer Part Number: C1608X7R1H224KT000N
footprint CAP-0603 (0603 (1608M) Capacitor)
pins: 1, 2

## C1608X7R1H333KT000N
designator C?  Capacitance: 33nF  (hidden comment: *)
Capacitor, Ceramic (MLCC), 33nF, ±10%, 50V, X7R, ±10%, SMD 0603; Manufacturer: TDK; Manufacturer Part Number: C1608X7R1H333KT000N
footprint CAP-0603 (0603 (1608M) Capacitor)
pins: 1, 2

## C1608X7R1H334KT000E
designator C?  Capacitance: 330nF  (hidden comment: *)
Capacitor, Ceramic (MLCC), 330nF, ±10%, 50V, X7R, ±10%, SMD 0603; Manufacturer: TDK; Manufacturer Part Number: C1608X7R1H334KT000E
footprint CAP-0603 (0603 (1608M) Capacitor)
pins: 1, 2

## C1608X7R1H472KT000N
designator C?  Capacitance: 4.7nF  (hidden comment: *)
Capacitor, Ceramic (MLCC), 4.7nF, ±10%, 50V, X7R, ±10%, SMD 0603; Manufacturer: TDK; Manufacturer Part Number: C1608X7R1H472KT000N
footprint CAP-0603 (0603 (1608M) Capacitor)
pins: 1, 2

## C1608X7R1H473KT000N
designator C?  Capacitance: 47nF  (hidden comment: *)
Capacitor, Ceramic (MLCC), 47nF, ±10%, 50V, X7R, ±10%, SMD 0603; Manufacturer: TDK; Manufacturer Part Number: C1608X7R1H473KT000N
footprint CAP-0603 (0603 (1608M) Capacitor)
pins: 1, 2

## C1608X7R1H474KT000E
designator C?  Capacitance: 470nF  (hidden comment: *)
Capacitor, Ceramic (MLCC), 470nF, ±10%, 50V, X7R, ±10%, SMD 0603; Manufacturer: TDK; Manufacturer Part Number: C1608X7R1H474KT000E
footprint CAP-0603 (0603 (1608M) Capacitor)
pins: 1, 2

## C1608X7R1H683KT000N
designator C?  Capacitance: 68nF  (hidden comment: *)
Capacitor, Ceramic (MLCC), 68nF, ±10%, 50V, X7R, ±10%, SMD 0603; Manufacturer: TDK; Manufacturer Part Number: C1608X7R1H683KT000N
footprint CAP-0603 (0603 (1608M) Capacitor)
pins: 1, 2

## C1608X7R2A102KT000N
designator C?  Capacitance: 1nF  (hidden comment: *)
Capacitor, Ceramic (MLCC), 1nF, ±10%, 100V, X7R, ±10%, SMD 0603; Manufacturer: TDK; Manufacturer Part Number: C1608X7R2A102KT000N
footprint CAP-0603 (0603 (1608M) Capacitor)
pins: 1, 2

## C1608X7R2A103KT000N
designator C?  Capacitance: 10nF  (hidden comment: *)
Capacitor, Ceramic (MLCC), 10nF, ±10%, 100V, X7R, ±10%, SMD 0603; Manufacturer: TDK; Manufacturer Part Number: C1608X7R2A103KT000N
footprint CAP-0603 (0603 (1608M) Capacitor)
pins: 1, 2

## C1608X7R2A222KT000N
designator C?  Capacitance: 2.2nF  (hidden comment: *)
Capacitor, Ceramic (MLCC), 2.2nF, ±10%, 100V, X7R, ±10%, SMD 0603; Manufacturer: TDK; Manufacturer Part Number: C1608X7R2A222KT000N
footprint CAP-0603 (0603 (1608M) Capacitor)
pins: 1, 2

## C1608X7R2A223KT000N
designator C?  Capacitance: 22nF  (hidden comment: *)
Capacitor, Ceramic (MLCC), 22nF, ±10%, 100V, X7R, ±10%, SMD 0603; Manufacturer: TDK; Manufacturer Part Number: C1608X7R2A223KT000N
footprint CAP-0603 (0603 (1608M) Capacitor)
pins: 1, 2

## C1608X7R2A472KT000N
designator C?  Capacitance: 4.7nF  (hidden comment: *)
Capacitor, Ceramic (MLCC), 4.7nF, ±10%, 100V, X7R, ±10%, SMD 0603; Manufacturer: TDK; Manufacturer Part Number: C1608X7R2A472KT000N
footprint CAP-0603 (0603 (1608M) Capacitor)
pins: 1, 2

## C1608X7R2A682KT000N
designator C?  Capacitance: 6.8nF  (hidden comment: *)
Capacitor, Ceramic (MLCC), 6.8nF, ±10%, 100V, X7R, ±10%, SMD 0603; Manufacturer: TDK; Manufacturer Part Number: C1608X7R2A682KT000N
footprint CAP-0603 (0603 (1608M) Capacitor)
pins: 1, 2

## C1608X7R102KGTS
designator C?  Capacitance: 1nF  (hidden comment: *)
Capacitor, Ceramic (MLCC), 1nF, ±10%, 50V, X7R, ±10%, SMD 0603; Manufacturer: Darfon Elec; Manufacturer Part Number: C1608X7R102KGTS
footprint CAP-0603 (0603 (1608M) Capacitor)
pins: 1, 2

## C1608X7R104KFTS
designator C?  Capacitance: 100nF  (hidden comment: *)
Capacitor, Ceramic (MLCC), 100nF, ±10%, 25V, X7R, ±10%, SMD 0603; Manufacturer: Darfon Elec; Manufacturer Part Number: C1608X7R104KFTS
footprint CAP-0603 (0603 (1608M) Capacitor)
pins: 1, 2

## C1608X7R104KGT
designator C?  Capacitance: 100nF  (hidden comment: *)
Capacitor, Ceramic (MLCC), 100nF, ±10%, 50V, X7R, ±10%, SMD 0603; Manufacturer: Darfon Elec; Manufacturer Part Number: C1608X7R104KGT
footprint CAP-0603 (0603 (1608M) Capacitor)
pins: 1, 2

## C1608X7R104KGTS
designator C?  Capacitance: 100nF  (hidden comment: *)
Capacitor, Ceramic (MLCC), 100nF, ±10%, 50V, X7R, ±10%, SMD 0603; Manufacturer: Darfon Elec; Manufacturer Part Number: C1608X7R104KGTS
footprint CAP-0603 (0603 (1608M) Capacitor)
pins: 1, 2

## C1608X7R104MGTS
designator C?  Capacitance: 100nF  (hidden comment: *)
Capacitor, Ceramic (MLCC), 100nF, ±20%, 50V, X7R, ±20%, SMD 0603; Manufacturer: Darfon Elec; Manufacturer Part Number: C1608X7R104MGTS
footprint CAP-0603 (0603 (1608M) Capacitor)
pins: 1, 2

## C1608X7R105KET
designator C?  Capacitance: 1uF  (hidden comment: *)
Capacitor, Ceramic (MLCC), 1uF, ±10%, 16V, X7R, ±10%, SMD 0603; Manufacturer: Darfon Elec; Manufacturer Part Number: C1608X7R105KET
footprint CAP-0603 (0603 (1608M) Capacitor)
pins: 1, 2

## C1608X7R105KETS
designator C?  Capacitance: 1uF  (hidden comment: *)
Capacitor, Ceramic (MLCC), 1uF, ±10%, 16V, X7R, ±10%, SMD 0603; Manufacturer: Darfon Elec; Manufacturer Part Number: C1608X7R105KETS
footprint CAP-0603 (0603 (1608M) Capacitor)
pins: 1, 2

## C1608X7R223KFTS
designator C?  Capacitance: 22nF  (hidden comment: *)
Capacitor, Ceramic (MLCC), 22nF, ±10%, 25V, X7R, ±10%, SMD 0603; Manufacturer: Darfon Elec; Manufacturer Part Number: C1608X7R223KFTS
footprint CAP-0603 (0603 (1608M) Capacitor)
pins: 1, 2

## C1608X7R223KGTS
designator C?  Capacitance: 22nF  (hidden comment: *)
Capacitor, Ceramic (MLCC), 22nF, ±10%, 50V, X7R, ±10%, SMD 0603; Manufacturer: Darfon Elec; Manufacturer Part Number: C1608X7R223KGTS
footprint CAP-0603 (0603 (1608M) Capacitor)
pins: 1, 2

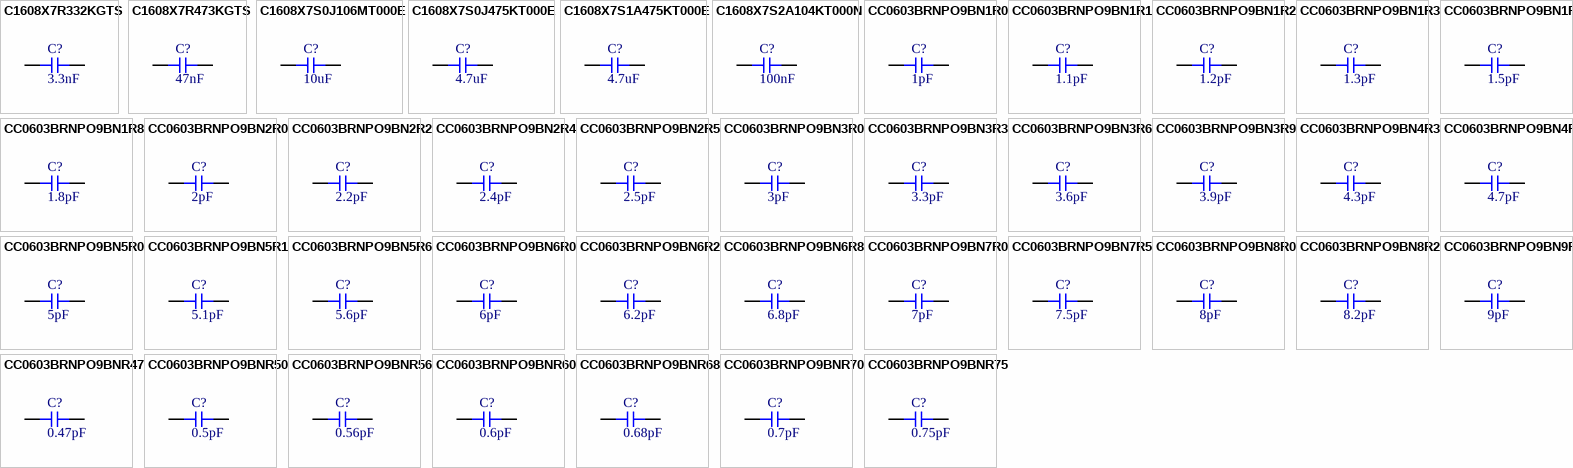
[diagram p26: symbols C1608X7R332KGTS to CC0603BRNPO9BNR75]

## C1608X7R332KGTS
designator C?  Capacitance: 3.3nF  (hidden comment: *)
Capacitor, Ceramic (MLCC), 3.3nF, ±10%, 50V, X7R, ±10%, SMD 0603; Manufacturer: Darfon Elec; Manufacturer Part Number: C1608X7R332KGTS
footprint CAP-0603 (0603 (1608M) Capacitor)
pins: 1, 2

## C1608X7R473KGTS
designator C?  Capacitance: 47nF  (hidden comment: *)
Capacitor, Ceramic (MLCC), 47nF, ±10%, 50V, X7R, ±10%, SMD 0603; Manufacturer: Darfon Elec; Manufacturer Part Number: C1608X7R473KGTS
footprint CAP-0603 (0603 (1608M) Capacitor)
pins: 1, 2

## C1608X7S0J106MT000E
designator C?  Capacitance: 10uF  (hidden comment: *)
Capacitor, Ceramic (MLCC), 10uF, ±20%, 6.3V, X7S, ±20%, SMD 0603; Manufacturer: TDK; Manufacturer Part Number: C1608X7S0J106MT000E
footprint CAP-0603 (0603 (1608M) Capacitor)
pins: 1, 2

## C1608X7S0J475KT000E
designator C?  Capacitance: 4.7uF  (hidden comment: *)
Capacitor, Ceramic (MLCC), 4.7uF, ±10%, 6.3V, X7S, ±10%, SMD 0603; Manufacturer: TDK; Manufacturer Part Number: C1608X7S0J475KT000E
footprint CAP-0603 (0603 (1608M) Capacitor)
pins: 1, 2

## C1608X7S1A475KT000E
designator C?  Capacitance: 4.7uF  (hidden comment: *)
Capacitor, Ceramic (MLCC), 4.7uF, ±10%, 10V, X7S, ±10%, SMD 0603; Manufacturer: TDK; Manufacturer Part Number: C1608X7S1A475KT000E
footprint CAP-0603 (0603 (1608M) Capacitor)
pins: 1, 2

## C1608X7S2A104KT000N
designator C?  Capacitance: 100nF  (hidden comment: *)
Capacitor, Ceramic (MLCC), 100nF, ±10%, 100V, X7S, ±10%, SMD 0603; Manufacturer: TDK; Manufacturer Part Number: C1608X7S2A104KT000N
footprint CAP-0603 (0603 (1608M) Capacitor)
pins: 1, 2

## CC0603BRNPO9BN1R0
designator C?  Capacitance: 1pF  (hidden comment: *)
Capacitor, Ceramic (MLCC), 1pF, ±0.1pF, 50V, NP0, ±0.1pF, SMD 0603; Manufacturer: YAGEO; Manufacturer Part Number: CC0603BRNPO9BN1R0
footprint CAP-0603 (0603 (1608M) Capacitor)
pins: 1, 2

## CC0603BRNPO9BN1R1
designator C?  Capacitance: 1.1pF  (hidden comment: *)
Capacitor, Ceramic (MLCC), 1.1pF, ±0.1pF, 50V, NP0, ±0.1pF, SMD 0603; Manufacturer: YAGEO; Manufacturer Part Number: CC0603BRNPO9BN1R1
footprint CAP-0603 (0603 (1608M) Capacitor)
pins: 1, 2

## CC0603BRNPO9BN1R2
designator C?  Capacitance: 1.2pF  (hidden comment: *)
Capacitor, Ceramic (MLCC), 1.2pF, ±0.1pF, 50V, NP0, ±0.1pF, SMD 0603; Manufacturer: YAGEO; Manufacturer Part Number: CC0603BRNPO9BN1R2
footprint CAP-0603 (0603 (1608M) Capacitor)
pins: 1, 2

## CC0603BRNPO9BN1R3
designator C?  Capacitance: 1.3pF  (hidden comment: *)
Capacitor, Ceramic (MLCC), 1.3pF, ±0.1pF, 50V, NP0, ±0.1pF, SMD 0603; Manufacturer: YAGEO; Manufacturer Part Number: CC0603BRNPO9BN1R3
footprint CAP-0603 (0603 (1608M) Capacitor)
pins: 1, 2

## CC0603BRNPO9BN1R5
designator C?  Capacitance: 1.5pF  (hidden comment: *)
Capacitor, Ceramic (MLCC), 1.5pF, ±0.1pF, 50V, NP0, ±0.1pF, SMD 0603; Manufacturer: YAGEO; Manufacturer Part Number: CC0603BRNPO9BN1R5
footprint CAP-0603 (0603 (1608M) Capacitor)
pins: 1, 2

## CC0603BRNPO9BN1R8
designator C?  Capacitance: 1.8pF  (hidden comment: *)
Capacitor, Ceramic (MLCC), 1.8pF, ±0.1pF, 50V, NP0, ±0.1pF, SMD 0603; Manufacturer: YAGEO; Manufacturer Part Number: CC0603BRNPO9BN1R8
footprint CAP-0603 (0603 (1608M) Capacitor)
pins: 1, 2

## CC0603BRNPO9BN2R0
designator C?  Capacitance: 2pF  (hidden comment: *)
Capacitor, Ceramic (MLCC), 2pF, ±0.1pF, 50V, NP0, ±0.1pF, SMD 0603; Manufacturer: YAGEO; Manufacturer Part Number: CC0603BRNPO9BN2R0
footprint CAP-0603 (0603 (1608M) Capacitor)
pins: 1, 2

## CC0603BRNPO9BN2R2
designator C?  Capacitance: 2.2pF  (hidden comment: *)
Capacitor, Ceramic (MLCC), 2.2pF, ±0.1pF, 50V, NP0, ±0.1pF, SMD 0603; Manufacturer: YAGEO; Manufacturer Part Number: CC0603BRNPO9BN2R2
footprint CAP-0603 (0603 (1608M) Capacitor)
pins: 1, 2

## CC0603BRNPO9BN2R4
designator C?  Capacitance: 2.4pF  (hidden comment: *)
Capacitor, Ceramic (MLCC), 2.4pF, ±0.1pF, 50V, NP0, ±0.1pF, SMD 0603; Manufacturer: YAGEO; Manufacturer Part Number: CC0603BRNPO9BN2R4
footprint CAP-0603 (0603 (1608M) Capacitor)
pins: 1, 2

## CC0603BRNPO9BN2R5
designator C?  Capacitance: 2.5pF  (hidden comment: *)
Capacitor, Ceramic (MLCC), 2.5pF, ±0.1pF, 50V, NP0, ±0.1pF, SMD 0603; Manufacturer: YAGEO; Manufacturer Part Number: CC0603BRNPO9BN2R5
footprint CAP-0603 (0603 (1608M) Capacitor)
pins: 1, 2

## CC0603BRNPO9BN3R0
designator C?  Capacitance: 3pF  (hidden comment: *)
Capacitor, Ceramic (MLCC), 3pF, ±0.1pF, 50V, NP0, ±0.1pF, SMD 0603; Manufacturer: YAGEO; Manufacturer Part Number: CC0603BRNPO9BN3R0
footprint CAP-0603 (0603 (1608M) Capacitor)
pins: 1, 2

## CC0603BRNPO9BN3R3
designator C?  Capacitance: 3.3pF  (hidden comment: *)
Capacitor, Ceramic (MLCC), 3.3pF, ±0.1pF, 50V, NP0, ±0.1pF, SMD 0603; Manufacturer: YAGEO; Manufacturer Part Number: CC0603BRNPO9BN3R3
footprint CAP-0603 (0603 (1608M) Capacitor)
pins: 1, 2

## CC0603BRNPO9BN3R6
designator C?  Capacitance: 3.6pF  (hidden comment: *)
Capacitor, Ceramic (MLCC), 3.6pF, ±0.1pF, 50V, NP0, ±0.1pF, SMD 0603; Manufacturer: YAGEO; Manufacturer Part Number: CC0603BRNPO9BN3R6
footprint CAP-0603 (0603 (1608M) Capacitor)
pins: 1, 2

## CC0603BRNPO9BN3R9
designator C?  Capacitance: 3.9pF  (hidden comment: *)
Capacitor, Ceramic (MLCC), 3.9pF, ±0.1pF, 50V, NP0, ±0.1pF, SMD 0603; Manufacturer: YAGEO; Manufacturer Part Number: CC0603BRNPO9BN3R9
footprint CAP-0603 (0603 (1608M) Capacitor)
pins: 1, 2

## CC0603BRNPO9BN4R3
designator C?  Capacitance: 4.3pF  (hidden comment: *)
Capacitor, Ceramic (MLCC), 4.3pF, ±0.1pF, 50V, NP0, ±0.1pF, SMD 0603; Manufacturer: YAGEO; Manufacturer Part Number: CC0603BRNPO9BN4R3
footprint CAP-0603 (0603 (1608M) Capacitor)
pins: 1, 2

## CC0603BRNPO9BN4R7
designator C?  Capacitance: 4.7pF  (hidden comment: *)
Capacitor, Ceramic (MLCC), 4.7pF, ±0.1pF, 50V, NP0, ±0.1pF, SMD 0603; Manufacturer: YAGEO; Manufacturer Part Number: CC0603BRNPO9BN4R7
footprint CAP-0603 (0603 (1608M) Capacitor)
pins: 1, 2

## CC0603BRNPO9BN5R0
designator C?  Capacitance: 5pF  (hidden comment: *)
Capacitor, Ceramic (MLCC), 5pF, ±0.1pF, 50V, NP0, ±0.1pF, SMD 0603; Manufacturer: YAGEO; Manufacturer Part Number: CC0603BRNPO9BN5R0
footprint CAP-0603 (0603 (1608M) Capacitor)
pins: 1, 2

## CC0603BRNPO9BN5R1
designator C?  Capacitance: 5.1pF  (hidden comment: *)
Capacitor, Ceramic (MLCC), 5.1pF, ±0.1pF, 50V, NP0, ±0.1pF, SMD 0603; Manufacturer: YAGEO; Manufacturer Part Number: CC0603BRNPO9BN5R1
footprint CAP-0603 (0603 (1608M) Capacitor)
pins: 1, 2

## CC0603BRNPO9BN5R6
designator C?  Capacitance: 5.6pF  (hidden comment: *)
Capacitor, Ceramic (MLCC), 5.6pF, ±0.1pF, 50V, NP0, ±0.1pF, SMD 0603; Manufacturer: YAGEO; Manufacturer Part Number: CC0603BRNPO9BN5R6
footprint CAP-0603 (0603 (1608M) Capacitor)
pins: 1, 2

## CC0603BRNPO9BN6R0
designator C?  Capacitance: 6pF  (hidden comment: *)
Capacitor, Ceramic (MLCC), 6pF, ±0.1pF, 50V, NP0, ±0.1pF, SMD 0603; Manufacturer: YAGEO; Manufacturer Part Number: CC0603BRNPO9BN6R0
footprint CAP-0603 (0603 (1608M) Capacitor)
pins: 1, 2

## CC0603BRNPO9BN6R2
designator C?  Capacitance: 6.2pF  (hidden comment: *)
Capacitor, Ceramic (MLCC), 6.2pF, ±0.1pF, 50V, NP0, ±0.1pF, SMD 0603; Manufacturer: YAGEO; Manufacturer Part Number: CC0603BRNPO9BN6R2
footprint CAP-0603 (0603 (1608M) Capacitor)
pins: 1, 2

## CC0603BRNPO9BN6R8
designator C?  Capacitance: 6.8pF  (hidden comment: *)
Capacitor, Ceramic (MLCC), 6.8pF, ±0.1pF, 50V, NP0, ±0.1pF, SMD 0603; Manufacturer: YAGEO; Manufacturer Part Number: CC0603BRNPO9BN6R8
footprint CAP-0603 (0603 (1608M) Capacitor)
pins: 1, 2

## CC0603BRNPO9BN7R0
designator C?  Capacitance: 7pF  (hidden comment: *)
Capacitor, Ceramic (MLCC), 7pF, ±0.1pF, 50V, NP0, ±0.1pF, SMD 0603; Manufacturer: YAGEO; Manufacturer Part Number: CC0603BRNPO9BN7R0
footprint CAP-0603 (0603 (1608M) Capacitor)
pins: 1, 2

## CC0603BRNPO9BN7R5
designator C?  Capacitance: 7.5pF  (hidden comment: *)
Capacitor, Ceramic (MLCC), 7.5pF, ±0.1pF, 50V, NP0, ±0.1pF, SMD 0603; Manufacturer: YAGEO; Manufacturer Part Number: CC0603BRNPO9BN7R5
footprint CAP-0603 (0603 (1608M) Capacitor)
pins: 1, 2

## CC0603BRNPO9BN8R0
designator C?  Capacitance: 8pF  (hidden comment: *)
Capacitor, Ceramic (MLCC), 8pF, ±0.1pF, 50V, NP0, ±0.1pF, SMD 0603; Manufacturer: YAGEO; Manufacturer Part Number: CC0603BRNPO9BN8R0
footprint CAP-0603 (0603 (1608M) Capacitor)
pins: 1, 2

## CC0603BRNPO9BN8R2
designator C?  Capacitance: 8.2pF  (hidden comment: *)
Capacitor, Ceramic (MLCC), 8.2pF, ±0.1pF, 50V, NP0, ±0.1pF, SMD 0603; Manufacturer: YAGEO; Manufacturer Part Number: CC0603BRNPO9BN8R2
footprint CAP-0603 (0603 (1608M) Capacitor)
pins: 1, 2

## CC0603BRNPO9BN9R0
designator C?  Capacitance: 9pF  (hidden comment: *)
Capacitor, Ceramic (MLCC), 9pF, ±0.1pF, 50V, NP0, ±0.1pF, SMD 0603; Manufacturer: YAGEO; Manufacturer Part Number: CC0603BRNPO9BN9R0
footprint CAP-0603 (0603 (1608M) Capacitor)
pins: 1, 2

## CC0603BRNPO9BNR47
designator C?  Capacitance: 0.47pF  (hidden comment: *)
Capacitor, Ceramic (MLCC), 0.47pF, ±0.1pF, 50V, NP0, ±0.1pF, SMD 0603; Manufacturer: YAGEO; Manufacturer Part Number: CC0603BRNPO9BNR47
footprint CAP-0603 (0603 (1608M) Capacitor)
pins: 1, 2

## CC0603BRNPO9BNR50
designator C?  Capacitance: 0.5pF  (hidden comment: *)
Capacitor, Ceramic (MLCC), 0.5pF, ±0.1pF, 50V, NP0, ±0.1pF, SMD 0603; Manufacturer: YAGEO; Manufacturer Part Number: CC0603BRNPO9BNR50
footprint CAP-0603 (0603 (1608M) Capacitor)
pins: 1, 2

## CC0603BRNPO9BNR56
designator C?  Capacitance: 0.56pF  (hidden comment: *)
Capacitor, Ceramic (MLCC), 0.56pF, ±0.1pF, 50V, NP0, ±0.1pF, SMD 0603; Manufacturer: YAGEO; Manufacturer Part Number: CC0603BRNPO9BNR56
footprint CAP-0603 (0603 (1608M) Capacitor)
pins: 1, 2

## CC0603BRNPO9BNR60
designator C?  Capacitance: 0.6pF  (hidden comment: *)
Capacitor, Ceramic (MLCC), 0.6pF, ±0.1pF, 50V, NP0, ±0.1pF, SMD 0603; Manufacturer: YAGEO; Manufacturer Part Number: CC0603BRNPO9BNR60
footprint CAP-0603 (0603 (1608M) Capacitor)
pins: 1, 2

## CC0603BRNPO9BNR68
designator C?  Capacitance: 0.68pF  (hidden comment: *)
Capacitor, Ceramic (MLCC), 0.68pF, ±0.1pF, 50V, NP0, ±0.1pF, SMD 0603; Manufacturer: YAGEO; Manufacturer Part Number: CC0603BRNPO9BNR68
footprint CAP-0603 (0603 (1608M) Capacitor)
pins: 1, 2

## CC0603BRNPO9BNR70
designator C?  Capacitance: 0.7pF  (hidden comment: *)
Capacitor, Ceramic (MLCC), 0.7pF, ±0.1pF, 50V, NP0, ±0.1pF, SMD 0603; Manufacturer: YAGEO; Manufacturer Part Number: CC0603BRNPO9BNR70
footprint CAP-0603 (0603 (1608M) Capacitor)
pins: 1, 2

## CC0603BRNPO9BNR75
designator C?  Capacitance: 0.75pF  (hidden comment: *)
Capacitor, Ceramic (MLCC), 0.75pF, ±0.1pF, 50V, NP0, ±0.1pF, SMD 0603; Manufacturer: YAGEO; Manufacturer Part Number: CC0603BRNPO9BNR75
footprint CAP-0603 (0603 (1608M) Capacitor)
pins: 1, 2

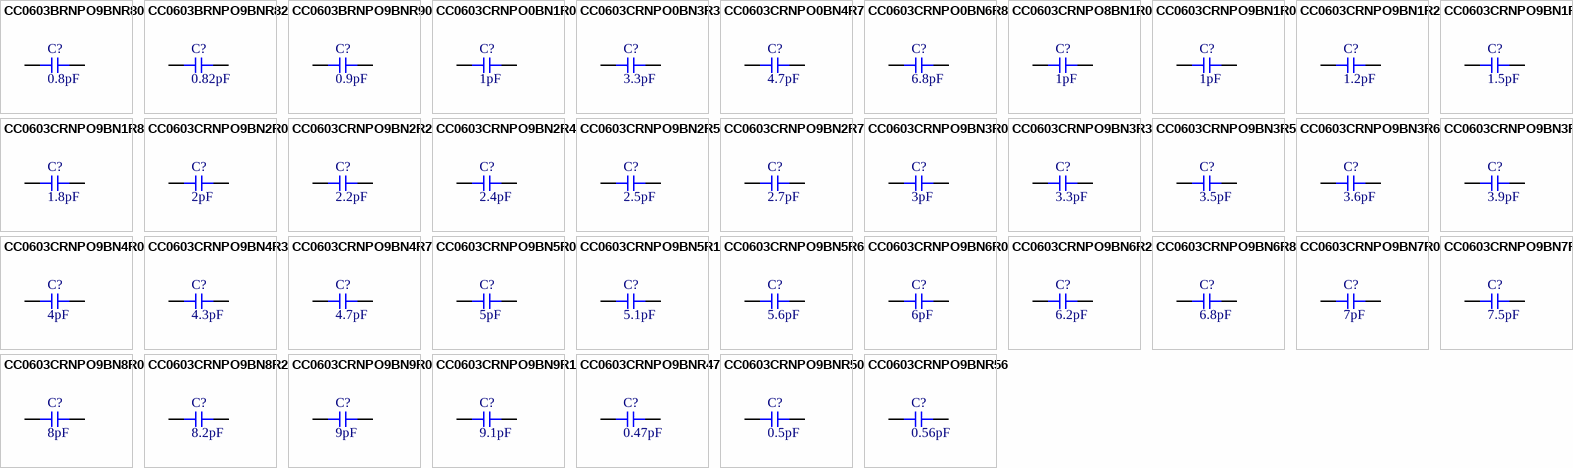
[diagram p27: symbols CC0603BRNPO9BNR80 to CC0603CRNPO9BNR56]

## CC0603BRNPO9BNR80
designator C?  Capacitance: 0.8pF  (hidden comment: *)
Capacitor, Ceramic (MLCC), 0.8pF, ±0.1pF, 50V, NP0, ±0.1pF, SMD 0603; Manufacturer: YAGEO; Manufacturer Part Number: CC0603BRNPO9BNR80
footprint CAP-0603 (0603 (1608M) Capacitor)
pins: 1, 2

## CC0603BRNPO9BNR82
designator C?  Capacitance: 0.82pF  (hidden comment: *)
Capacitor, Ceramic (MLCC), 0.82pF, ±0.1pF, 50V, NP0, ±0.1pF, SMD 0603; Manufacturer: YAGEO; Manufacturer Part Number: CC0603BRNPO9BNR82
footprint CAP-0603 (0603 (1608M) Capacitor)
pins: 1, 2

## CC0603BRNPO9BNR90
designator C?  Capacitance: 0.9pF  (hidden comment: *)
Capacitor, Ceramic (MLCC), 0.9pF, ±0.1pF, 50V, NP0, ±0.1pF, SMD 0603; Manufacturer: YAGEO; Manufacturer Part Number: CC0603BRNPO9BNR90
footprint CAP-0603 (0603 (1608M) Capacitor)
pins: 1, 2

## CC0603CRNPO0BN1R0
designator C?  Capacitance: 1pF  (hidden comment: *)
Capacitor, Ceramic (MLCC), 1pF, ±0.25pF, 100V, NP0, ±0.25pF, SMD 0603; Manufacturer: YAGEO; Manufacturer Part Number: CC0603CRNPO0BN1R0
footprint CAP-0603 (0603 (1608M) Capacitor)
pins: 1, 2

## CC0603CRNPO0BN3R3
designator C?  Capacitance: 3.3pF  (hidden comment: *)
Capacitor, Ceramic (MLCC), 3.3pF, ±0.25pF, 100V, NP0, ±0.25pF, SMD 0603; Manufacturer: YAGEO; Manufacturer Part Number: CC0603CRNPO0BN3R3
footprint CAP-0603 (0603 (1608M) Capacitor)
pins: 1, 2

## CC0603CRNPO0BN4R7
designator C?  Capacitance: 4.7pF  (hidden comment: *)
Capacitor, Ceramic (MLCC), 4.7pF, ±0.25pF, 100V, NP0, ±0.25pF, SMD 0603; Manufacturer: YAGEO; Manufacturer Part Number: CC0603CRNPO0BN4R7
footprint CAP-0603 (0603 (1608M) Capacitor)
pins: 1, 2

## CC0603CRNPO0BN6R8
designator C?  Capacitance: 6.8pF  (hidden comment: *)
Capacitor, Ceramic (MLCC), 6.8pF, ±0.25pF, 100V, NP0, ±0.25pF, SMD 0603; Manufacturer: YAGEO; Manufacturer Part Number: CC0603CRNPO0BN6R8
footprint CAP-0603 (0603 (1608M) Capacitor)
pins: 1, 2

## CC0603CRNPO8BN1R0
designator C?  Capacitance: 1pF  (hidden comment: *)
Capacitor, Ceramic (MLCC), 1pF, ±0.25pF, 25V, NP0, ±0.25pF, SMD 0603; Manufacturer: YAGEO; Manufacturer Part Number: CC0603CRNPO8BN1R0
footprint CAP-0603 (0603 (1608M) Capacitor)
pins: 1, 2

## CC0603CRNPO9BN1R0
designator C?  Capacitance: 1pF  (hidden comment: *)
Capacitor, Ceramic (MLCC), 1pF, ±0.25pF, 50V, NP0, ±0.25pF, SMD 0603; Manufacturer: YAGEO; Manufacturer Part Number: CC0603CRNPO9BN1R0
footprint CAP-0603 (0603 (1608M) Capacitor)
pins: 1, 2

## CC0603CRNPO9BN1R2
designator C?  Capacitance: 1.2pF  (hidden comment: *)
Capacitor, Ceramic (MLCC), 1.2pF, ±0.25pF, 50V, NP0, ±0.25pF, SMD 0603; Manufacturer: YAGEO; Manufacturer Part Number: CC0603CRNPO9BN1R2
footprint CAP-0603 (0603 (1608M) Capacitor)
pins: 1, 2

## CC0603CRNPO9BN1R5
designator C?  Capacitance: 1.5pF  (hidden comment: *)
Capacitor, Ceramic (MLCC), 1.5pF, ±0.25pF, 50V, NP0, ±0.25pF, SMD 0603; Manufacturer: YAGEO; Manufacturer Part Number: CC0603CRNPO9BN1R5
footprint CAP-0603 (0603 (1608M) Capacitor)
pins: 1, 2

## CC0603CRNPO9BN1R8
designator C?  Capacitance: 1.8pF  (hidden comment: *)
Capacitor, Ceramic (MLCC), 1.8pF, ±0.25pF, 50V, NP0, ±0.25pF, SMD 0603; Manufacturer: YAGEO; Manufacturer Part Number: CC0603CRNPO9BN1R8
footprint CAP-0603 (0603 (1608M) Capacitor)
pins: 1, 2

## CC0603CRNPO9BN2R0
designator C?  Capacitance: 2pF  (hidden comment: *)
Capacitor, Ceramic (MLCC), 2pF, ±0.25pF, 50V, NP0, ±0.25pF, SMD 0603; Manufacturer: YAGEO; Manufacturer Part Number: CC0603CRNPO9BN2R0
footprint CAP-0603 (0603 (1608M) Capacitor)
pins: 1, 2

## CC0603CRNPO9BN2R2
designator C?  Capacitance: 2.2pF  (hidden comment: *)
Capacitor, Ceramic (MLCC), 2.2pF, ±0.25pF, 50V, NP0, ±0.25pF, SMD 0603; Manufacturer: YAGEO; Manufacturer Part Number: CC0603CRNPO9BN2R2
footprint CAP-0603 (0603 (1608M) Capacitor)
pins: 1, 2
